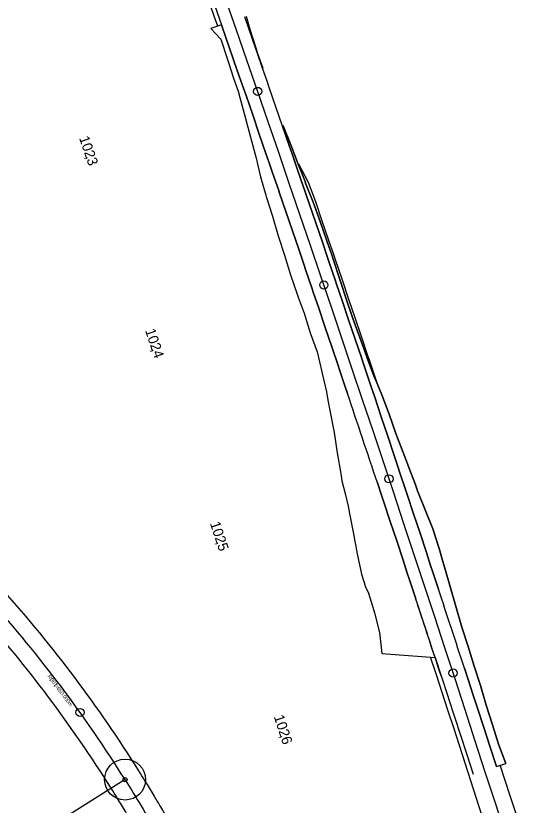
# Model space of a CAD drawing. Extents: x -678487 to -674601, y -1104811 to -1093295.
# Drawn here: x -676665.5 to -676418.4, y -1099310.5 to -1098924.5 of the extents above; entities that cross this region are included whole.
import ezdxf

# ---------------------------------------------------------------- set-up
doc = ezdxf.new("R2010")
doc.units = 0
for name, color, linetype in [('00_MiNGO', 7, 'Continuous'), ('SOxx02xx_Koleje_hlavní_body_Popis', 7, 'Continuous'), ('SOxx02xx_Koleje_hlavní_body_Popis10', 7, 'Continuous'), ('SOxx02xx_Koleje_param další_Popis', 7, 'Continuous'), ('SOxx02xx_Staničení_Popis', 7, 'Continuous'), ('SOxxxxxx_Osa_bod_P', 7, 'Continuous'), ('SOxxxxxx_Staničení_Popis', 7, 'Continuous'), ('SOxxxxxx_ŽSp_hrana', 7, 'Continuous'), ('SOxxxxxx_ŽSp_násyp_hrana', 7, 'Continuous'), ('SOxxxxxx_ŽSp_násyp_plocha', 7, 'Continuous'), ('SOxxxxxx_ŽSp_zářez_hrana', 7, 'Continuous')]:
    doc.layers.add(name, color=color, linetype=linetype)

msp = doc.modelspace()

# ---------------------------------------------------------------- linework, layer by layer
at = {"layer": '00_MiNGO'}
for centre, radius, start, end in [((-693563.22, -1104838.51), 17994.25, 19.170332, 19.431214), ((-677162.76, -1099643.36), 658, 32.09424, 41.75158), ((-677162.76, -1099643.36), 642, 32.09424, 41.75158), ((-693563.22, -1104838.51), 17994.25, 16.282565, 18.133556), ((-693563.22, -1104838.51), 18010.25, 16.348631, 17.939981)]:
    msp.add_arc(centre, radius, start, end, dxfattribs=at)
for points in [[(-676556.3, -1099381.6), (-676560.18, -1099374.22), (-676564.05, -1099366.83), (-676571.89, -1099352.06), (-676575.85, -1099344.69), (-676583.93, -1099329.99), (-676588.04, -1099322.67), (-676594.38, -1099311.76), (-676596.52, -1099308.14), (-676600.87, -1099300.93), (-676603.08, -1099297.33), (-676605.32, -1099293.76)], [(-676570.47, -1099389.03), (-676574.34, -1099381.66), (-676578.21, -1099374.29), (-676586, -1099359.61), (-676589.93, -1099352.3), (-676597.9, -1099337.79), (-676601.95, -1099330.58), (-676608.18, -1099319.87), (-676610.28, -1099316.32), (-676614.53, -1099309.26), (-676616.68, -1099305.75), (-676618.87, -1099302.26)]]:
    msp.add_open_spline(points, degree=3, dxfattribs=at)
at = {"layer": 'SOxx02xx_Koleje_hlavní_body_Popis'}
for q in [(-676662.92, -1099329.89), (-676612.09, -1099298.01)]:
    msp.add_line((-676612.09, -1099298.01), q, dxfattribs=at)
msp.add_circle((-676612.09, -1099298.01), 1, dxfattribs=at)
at = {"layer": 'SOxx02xx_Koleje_hlavní_body_Popis10'}
msp.add_line((-676612.09, -1099298.01), (-676612.09, -1099298.01), dxfattribs=at)
msp.add_circle((-676612.09, -1099298.01), 10, dxfattribs=at)
at = {"layer": 'SOxx02xx_Staničení_Popis'}
msp.add_circle((-676634.12, -1099265.16), 2, dxfattribs=at)
at = {"layer": 'SOxxxxxx_Osa_bod_P'}
for centre, radius, start, end in [((-693563.22, -1104838.51), 18002.25, 14.227837, 20.731742), ((-677162.76, -1099643.36), 650, 32.09424, 41.79045)]:
    msp.add_arc(centre, radius, start, end, dxfattribs=at)
msp.add_open_spline([(-676612.09, -1099298.01), (-676609.88, -1099301.54), (-676605.52, -1099308.64), (-676597.04, -1099322.99), (-676586.83, -1099341.15), (-676576.98, -1099359.51), (-676569.2, -1099374.25), (-676565.32, -1099381.63), (-676563.39, -1099385.32)], degree=3, dxfattribs=at)
at = {"layer": 'SOxxxxxx_Staničení_Popis'}
for p, q in [((-676547.28, -1098961.53), (-676547.28, -1098961.53)), ((-676514.9, -1099056.14), (-676514.9, -1099056.14)), ((-676483.04, -1099150.93), (-676483.04, -1099150.93)), ((-676451.71, -1099245.9), (-676451.71, -1099245.9)), ((-676634.12, -1099265.16), (-676634.12, -1099265.16))]:
    msp.add_line(p, q, dxfattribs=at)
for centre in [(-676547.28, -1098961.53), (-676514.9, -1099056.14), (-676483.04, -1099150.93), (-676451.71, -1099245.9), (-676634.12, -1099265.16)]:
    msp.add_circle(centre, 2, dxfattribs=at)
at = {"layer": 'SOxxxxxx_ŽSp_hrana'}
for points in [[(-676592.02, -1098851.61), (-676564.93, -1098928.95), (-676562.78, -1098935.16), (-676559.5, -1098944.6), (-676558.84, -1098946.5), (-676556.23, -1098954.05), (-676554, -1098960.48), (-676552.96, -1098963.5), (-676549.7, -1098972.95), (-676546.45, -1098982.4), (-676543.2, -1098991.85), (-676541.6, -1098996.5), (-676539.95, -1099001.31), (-676536.97, -1099010.02), (-676536.71, -1099010.76), (-676533.48, -1099020.22), (-676530.25, -1099029.68), (-676527.02, -1099039.14), (-676524.5, -1099046.55), (-676523.8, -1099048.61), (-676520.59, -1099058.08), (-676520.07, -1099059.6), (-676517.38, -1099067.54), (-676514.18, -1099077.01), (-676510.98, -1099086.48), (-676507.79, -1099095.96), (-676507.55, -1099096.65), (-676504.6, -1099105.43), (-676503.33, -1099109.23)], [(-676458.85, -1099204.87), (-676461.6, -1099196.51), (-676462.68, -1099193.24), (-676464.74, -1099187.01), (-676467.88, -1099177.52), (-676471.03, -1099168.02), (-676474.18, -1099158.53), (-676475.32, -1099155.11), (-676477.34, -1099149.04), (-676479.35, -1099143), (-676480.5, -1099139.55), (-676483.67, -1099130.06), (-676486.84, -1099120.57), (-676490.02, -1099111.09), (-676491.93, -1099105.4), (-676493.21, -1099101.6), (-676496.16, -1099092.82), (-676496.4, -1099092.12), (-676499.59, -1099082.64), (-676502.79, -1099073.16), (-676506, -1099063.69), (-676508.69, -1099055.74), (-676509.21, -1099054.21), (-676512.42, -1099044.74), (-676513.12, -1099042.68), (-676515.64, -1099035.27), (-676518.87, -1099025.8), (-676522.1, -1099016.34), (-676525.34, -1099006.87), (-676525.59, -1099006.12), (-676528.58, -1098997.41), (-676530.23, -1098992.6), (-676531.83, -1098987.95), (-676535.08, -1098978.49), (-676538.34, -1098969.03), (-676541.6, -1098959.57), (-676542.64, -1098956.56), (-676544.87, -1098950.12), (-676547.48, -1098942.56), (-676548.14, -1098940.66), (-676551.42, -1098931.21), (-676553.58, -1098925)], [(-676488.74, -1099152.83), (-676486.72, -1099158.91), (-676485.59, -1099162.32), (-676482.44, -1099171.81), (-676479.29, -1099181.3), (-676476.15, -1099190.79), (-676474.1, -1099197), (-676473.02, -1099200.28), (-676470.26, -1099208.63), (-676469.89, -1099209.77)], [(-676430.53, -1099291.6), (-676433.61, -1099282.08), (-676436.7, -1099272.57), (-676439.79, -1099263.05), (-676442.52, -1099254.68), (-676442.89, -1099253.54), (-676446, -1099244.03), (-676446.17, -1099243.52)], [(-676457.59, -1099247.25), (-676457.42, -1099247.77), (-676454.32, -1099257.27), (-676453.95, -1099258.41), (-676451.22, -1099266.77), (-676448.13, -1099276.28), (-676445.04, -1099285.79), (-676441.96, -1099295.3)]]:
    msp.add_lwpolyline(points, dxfattribs=at)
for radius, start, end in [(17996.24, 18.417387, 18.563773), (18008.26, 18.100835, 18.23024), (17996.24, 18.100835, 18.226424)]:
    msp.add_arc((-693563.22, -1104838.51), radius, start, end, dxfattribs=at)
at = {"layer": 'SOxxxxxx_ŽSp_násyp_hrana'}
for p, q in [((-676552.85, -1098924.75), (-676551.07, -1098931.09)), ((-676570.16, -1098930.76), (-676565.24, -1098936.01)), ((-676551.07, -1098931.09), (-676548.06, -1098940.64)), ((-676565.24, -1098936.01), (-676562.12, -1098945.51)), ((-676548.06, -1098940.64), (-676547.43, -1098942.55)), ((-676547.43, -1098942.55), (-676544.76, -1098950.08)), ((-676562.12, -1098945.51), (-676561.49, -1098947.42)), ((-676561.49, -1098947.42), (-676559.12, -1098955.05)), ((-676559.12, -1098955.05), (-676556.84, -1098961.46)), ((-676556.84, -1098961.46), (-676555.91, -1098964.51)), ((-676555.91, -1098964.51), (-676553.32, -1098974.19)), ((-676553.32, -1098974.19), (-676550.73, -1098983.87)), ((-676534.73, -1098978.36), (-676531.1, -1098987.7)), ((-676550.73, -1098983.87), (-676548.23, -1098993.58)), ((-676531.1, -1098987.7), (-676529.32, -1098992.29)), ((-676548.23, -1098993.58), (-676547.06, -1098998.37)), ((-676529.32, -1098992.29), (-676527.48, -1098997.03)), ((-676527.48, -1098997.03), (-676524.11, -1099005.61)), ((-676547.06, -1098998.37), (-676545.8, -1099003.31)), ((-676545.8, -1099003.31), (-676543.28, -1099012.18)), ((-676524.11, -1099005.61), (-676523.82, -1099006.35)), ((-676523.82, -1099006.35), (-676520.16, -1099015.67)), ((-676543.28, -1099012.18), (-676543.05, -1099012.93)), ((-676543.05, -1099012.93), (-676540.03, -1099022.46)), ((-676520.16, -1099015.67), (-676516.74, -1099025.08)), ((-676540.03, -1099022.46), (-676537.3, -1099032.09)), ((-676516.74, -1099025.08), (-676513.46, -1099034.53)), ((-676537.3, -1099032.09), (-676534.17, -1099041.58)), ((-676513.46, -1099034.53), (-676510.89, -1099041.93)), ((-676534.17, -1099041.58), (-676531.84, -1099049.05)), ((-676510.89, -1099041.93), (-676510.18, -1099043.98)), ((-676510.18, -1099043.98), (-676507.08, -1099053.49)), ((-676531.84, -1099049.05), (-676531.23, -1099051.13)), ((-676531.23, -1099051.13), (-676528.01, -1099060.59)), ((-676507.08, -1099053.49), (-676506.58, -1099055.02)), ((-676506.58, -1099055.02), (-676503.99, -1099063.01)), ((-676528.01, -1099060.59), (-676527.45, -1099062.1)), ((-676527.45, -1099062.1), (-676524.47, -1099069.94)), ((-676503.99, -1099063.01), (-676500.76, -1099072.48)), ((-676524.47, -1099069.94), (-676521.61, -1099079.52)), ((-676500.76, -1099072.48), (-676497.36, -1099081.89)), ((-676521.61, -1099079.52), (-676518.1, -1099088.89)), ((-676497.36, -1099081.89), (-676493.93, -1099091.29)), ((-676518.1, -1099088.89), (-676515.89, -1099098.69)), ((-676493.93, -1099091.29), (-676493.68, -1099091.98)), ((-676493.68, -1099091.98), (-676490.39, -1099100.65)), ((-676515.89, -1099098.69), (-676515.75, -1099099.41)), ((-676515.75, -1099099.41), (-676513.62, -1099108.46)), ((-676490.39, -1099100.65), (-676488.84, -1099104.36)), ((-676488.84, -1099104.36), (-676486.54, -1099109.92)), ((-676513.62, -1099108.46), (-676512.89, -1099112.44)), ((-676486.54, -1099109.92), (-676483, -1099119.28)), ((-676512.89, -1099112.44), (-676511.81, -1099118.4)), ((-676511.81, -1099118.4), (-676509.92, -1099128.3)), ((-676483, -1099119.28), (-676479.67, -1099128.72)), ((-676509.92, -1099128.3), (-676508.31, -1099138.29)), ((-676479.67, -1099128.72), (-676476.14, -1099138.09)), ((-676508.31, -1099138.29), (-676506.67, -1099148.28)), ((-676476.14, -1099138.09), (-676474.88, -1099141.51)), ((-676474.88, -1099141.51), (-676472.58, -1099147.45)), ((-676506.67, -1099148.28), (-676506.07, -1099151.91)), ((-676472.58, -1099147.45), (-676470.31, -1099153.45)), ((-676506.07, -1099151.91), (-676504.55, -1099158.1)), ((-676470.31, -1099153.45), (-676469.04, -1099156.82)), ((-676504.55, -1099158.1), (-676503.08, -1099164.35)), ((-676469.04, -1099156.82), (-676465.39, -1099166.15)), ((-676503.08, -1099164.35), (-676502.28, -1099167.87)), ((-676502.28, -1099167.87), (-676500.45, -1099177.78)), ((-676465.39, -1099166.15), (-676461.66, -1099175.46)), ((-676461.66, -1099175.46), (-676458.59, -1099184.98)), ((-676500.45, -1099177.78), (-676498.6, -1099187.69)), ((-676458.59, -1099184.98), (-676456.79, -1099191.29)), ((-676498.6, -1099187.69), (-676496.46, -1099197.5)), ((-676456.79, -1099191.29), (-676455.79, -1099194.6)), ((-676455.79, -1099194.6), (-676453.26, -1099203.04)), ((-676496.46, -1099197.5), (-676494.48, -1099203.73)), ((-676494.48, -1099203.73), (-676493.1, -1099206.9)), ((-676453.26, -1099203.04), (-676452.93, -1099204.19)), ((-676452.93, -1099204.19), (-676450.19, -1099213.82)), ((-676493.1, -1099206.9), (-676490.41, -1099215.27)), ((-676450.19, -1099213.82), (-676447.39, -1099223.43)), ((-676490.41, -1099215.27), (-676490.08, -1099216.42)), ((-676490.08, -1099216.42), (-676487.67, -1099226.14)), ((-676447.39, -1099223.43), (-676444.28, -1099232.95)), ((-676487.67, -1099226.14), (-676486.58, -1099236.29)), ((-676444.28, -1099232.95), (-676441.36, -1099242.52)), ((-676486.58, -1099236.29), (-676460.54, -1099238.27)), ((-676460.54, -1099238.27), (-676457.6, -1099247.26)), ((-676441.36, -1099242.52), (-676438.33, -1099252.05)), ((-676457.6, -1099247.26), (-676457.43, -1099247.77)), ((-676457.43, -1099247.77), (-676454.33, -1099257.27)), ((-676438.33, -1099252.05), (-676437.98, -1099253.2)), ((-676437.98, -1099253.2), (-676435.5, -1099261.66)), ((-676454.33, -1099257.27), (-676453.96, -1099258.41)), ((-676453.96, -1099258.41), (-676451.23, -1099266.78)), ((-676435.5, -1099261.66), (-676432.48, -1099271.19)), ((-676451.23, -1099266.78), (-676448.14, -1099276.28)), ((-676432.48, -1099271.19), (-676429.44, -1099280.73)), ((-676448.14, -1099276.28), (-676445.05, -1099285.79)), ((-676429.44, -1099280.73), (-676425.93, -1099290.11)), ((-676445.05, -1099285.79), (-676441.97, -1099295.3))]:
    msp.add_line(p, q, dxfattribs=at)
at = {"layer": 'SOxxxxxx_ŽSp_násyp_plocha'}
for p, q in [((-676564.93, -1098928.95), (-676570.16, -1098930.76)), ((-676534.73, -1098978.36), (-676535.08, -1098978.49)), ((-676430.53, -1099291.6), (-676425.93, -1099290.11))]:
    msp.add_line(p, q, dxfattribs=at)
for points in [[(-676570.16, -1098930.76), (-676565.24, -1098936.01), (-676562.12, -1098945.51), (-676561.49, -1098947.42), (-676559.12, -1098955.05), (-676556.84, -1098961.46), (-676555.91, -1098964.51), (-676553.32, -1098974.19), (-676550.73, -1098983.87), (-676548.23, -1098993.58), (-676547.06, -1098998.37), (-676545.8, -1099003.31), (-676543.28, -1099012.18), (-676543.05, -1099012.93), (-676540.03, -1099022.46), (-676537.3, -1099032.09), (-676534.17, -1099041.58), (-676531.84, -1099049.05), (-676531.23, -1099051.13), (-676528.01, -1099060.59), (-676527.45, -1099062.1), (-676524.47, -1099069.94), (-676521.61, -1099079.52), (-676518.1, -1099088.89), (-676515.89, -1099098.69), (-676515.75, -1099099.41), (-676513.62, -1099108.46), (-676512.89, -1099112.44), (-676511.81, -1099118.4), (-676509.92, -1099128.3), (-676508.31, -1099138.29), (-676506.67, -1099148.28), (-676506.07, -1099151.91), (-676504.55, -1099158.1), (-676503.08, -1099164.35), (-676502.28, -1099167.87), (-676500.45, -1099177.78), (-676498.6, -1099187.69), (-676496.46, -1099197.5), (-676494.48, -1099203.73), (-676493.1, -1099206.9), (-676490.41, -1099215.27), (-676490.08, -1099216.42), (-676487.67, -1099226.14), (-676486.58, -1099236.29), (-676460.53, -1099238.27)], [(-676503.33, -1099109.23), (-676504.6, -1099105.43), (-676507.55, -1099096.65), (-676507.79, -1099095.96), (-676510.98, -1099086.48), (-676514.18, -1099077.01), (-676517.38, -1099067.54), (-676520.07, -1099059.6), (-676520.59, -1099058.08), (-676523.8, -1099048.61), (-676524.5, -1099046.55), (-676527.02, -1099039.14), (-676530.25, -1099029.68), (-676533.48, -1099020.22), (-676536.71, -1099010.76), (-676536.97, -1099010.02), (-676539.95, -1099001.31), (-676541.6, -1098996.5), (-676543.2, -1098991.85), (-676546.45, -1098982.4), (-676549.7, -1098972.95), (-676552.96, -1098963.5), (-676554, -1098960.48), (-676556.23, -1098954.05), (-676558.84, -1098946.5), (-676559.5, -1098944.6), (-676562.78, -1098935.16), (-676564.93, -1098928.95)], [(-676535.08, -1098978.49), (-676531.83, -1098987.95), (-676530.23, -1098992.6), (-676528.58, -1098997.41), (-676525.59, -1099006.12), (-676525.34, -1099006.87), (-676522.1, -1099016.34), (-676518.87, -1099025.8), (-676515.64, -1099035.27), (-676513.12, -1099042.68), (-676512.42, -1099044.74), (-676509.21, -1099054.21), (-676508.69, -1099055.74), (-676506, -1099063.69), (-676502.79, -1099073.16), (-676499.59, -1099082.64), (-676496.4, -1099092.12), (-676496.16, -1099092.82), (-676493.21, -1099101.6), (-676491.93, -1099105.4), (-676490.02, -1099111.09), (-676486.84, -1099120.57), (-676483.67, -1099130.06), (-676480.5, -1099139.55), (-676479.35, -1099143), (-676477.34, -1099149.04), (-676475.32, -1099155.11), (-676474.18, -1099158.53), (-676471.03, -1099168.02), (-676467.88, -1099177.52), (-676464.74, -1099187.01), (-676462.68, -1099193.24), (-676461.6, -1099196.51), (-676458.85, -1099204.87)], [(-676425.93, -1099290.11), (-676429.44, -1099280.73), (-676432.48, -1099271.19), (-676435.5, -1099261.66), (-676437.98, -1099253.2), (-676438.33, -1099252.05), (-676441.36, -1099242.52), (-676444.28, -1099232.95), (-676447.39, -1099223.43), (-676450.19, -1099213.82), (-676452.93, -1099204.19), (-676453.26, -1099203.04), (-676455.79, -1099194.6), (-676456.79, -1099191.29), (-676458.59, -1099184.98), (-676461.66, -1099175.46), (-676465.39, -1099166.15), (-676469.04, -1099156.82), (-676470.31, -1099153.45), (-676472.58, -1099147.45), (-676474.88, -1099141.51), (-676476.14, -1099138.09), (-676479.67, -1099128.72), (-676483, -1099119.28), (-676486.54, -1099109.92), (-676488.84, -1099104.36), (-676490.39, -1099100.65), (-676493.68, -1099091.98), (-676493.93, -1099091.29), (-676497.36, -1099081.89), (-676500.76, -1099072.48), (-676503.99, -1099063.01), (-676506.58, -1099055.02), (-676507.08, -1099053.49), (-676510.18, -1099043.98), (-676510.89, -1099041.93), (-676513.46, -1099034.53), (-676516.74, -1099025.08), (-676520.16, -1099015.67), (-676523.82, -1099006.35), (-676524.11, -1099005.61), (-676527.48, -1098997.03), (-676529.32, -1098992.29), (-676531.1, -1098987.7), (-676534.73, -1098978.36)], [(-676469.89, -1099209.77), (-676470.26, -1099208.63), (-676473.02, -1099200.28), (-676474.1, -1099197), (-676476.15, -1099190.79), (-676479.29, -1099181.3), (-676482.44, -1099171.81), (-676485.59, -1099162.32), (-676486.72, -1099158.91), (-676488.74, -1099152.83)], [(-676446.17, -1099243.52), (-676446, -1099244.03), (-676442.89, -1099253.54), (-676442.52, -1099254.68), (-676439.79, -1099263.05), (-676436.7, -1099272.57), (-676433.61, -1099282.08), (-676430.53, -1099291.6)]]:
    msp.add_lwpolyline(points, dxfattribs=at)
for radius, start, end in [(17996.24, 18.417387, 18.563773), (18008.26, 18.100835, 18.23024), (17996.24, 18.130935, 18.226424)]:
    msp.add_arc((-693563.22, -1104838.51), radius, start, end, dxfattribs=at)
at = {"layer": 'SOxxxxxx_ŽSp_zářez_hrana'}
for p, q in [((-676527.31, -1098996.97), (-676522.58, -1099005.92)), ((-676522.58, -1099005.92), (-676519.05, -1099015.29)), ((-676519.05, -1099015.29), (-676515.82, -1099024.76)), ((-676515.82, -1099024.76), (-676512.6, -1099034.23)), ((-676512.6, -1099034.23), (-676510.07, -1099041.65)), ((-676510.07, -1099041.65), (-676509.37, -1099043.71)), ((-676509.37, -1099043.71), (-676506.16, -1099053.18)), ((-676506.16, -1099053.18), (-676505.64, -1099054.7)), ((-676505.64, -1099054.7), (-676502.95, -1099062.66)), ((-676502.95, -1099062.66), (-676499.74, -1099072.13)), ((-676499.74, -1099072.13), (-676496.54, -1099081.61)), ((-676496.54, -1099081.61), (-676493.35, -1099091.09)), ((-676493.35, -1099091.09), (-676493.11, -1099091.79)), ((-676493.11, -1099091.79), (-676490.16, -1099100.58)), ((-676490.16, -1099100.58), (-676488.88, -1099104.38))]:
    msp.add_line(p, q, dxfattribs=at)

# ---------------------------------------------------------------- texts
at = {"layer": 'SOxx02xx_Koleje_param další_Popis'}
for s, p in [('R(', (-676650.14, -1099247.54)), ('901', (-676648.83, -1099249.28)), (')=', (-676646.77, -1099252.03)), ('650,000m', (-676645.63, -1099253.54))]:
    msp.add_text(s, height=1.8, rotation=306.9423, dxfattribs=at).set_placement(p)
at = {"layer": 'SOxxxxxx_Staničení_Popis'}
for s, rotation, p in [('102', 289.0539, (-676634.65, -1098984.27)), (',', 289.0539, (-676631.53, -1098993.3)), ('3', 289.0539, (-676631.01, -1098994.81)), ('102', 288.7357, (-676602.39, -1099078.4)), (',', 288.7357, (-676599.32, -1099087.45)), ('4', 288.7357, (-676598.81, -1099088.96)), ('102', 288.4174, (-676570.66, -1099172.68)), (',', 288.4174, (-676567.64, -1099181.75)), ('5', 288.4174, (-676567.14, -1099183.26)), ('102', 288.0991, (-676539.44, -1099267.18)), (',', 288.0991, (-676536.47, -1099276.26)), ('6', 288.0991, (-676535.98, -1099277.78))]:
    msp.add_text(s, height=5, rotation=rotation, dxfattribs=at).set_placement(p)

doc.saveas('drawing.dxf')
